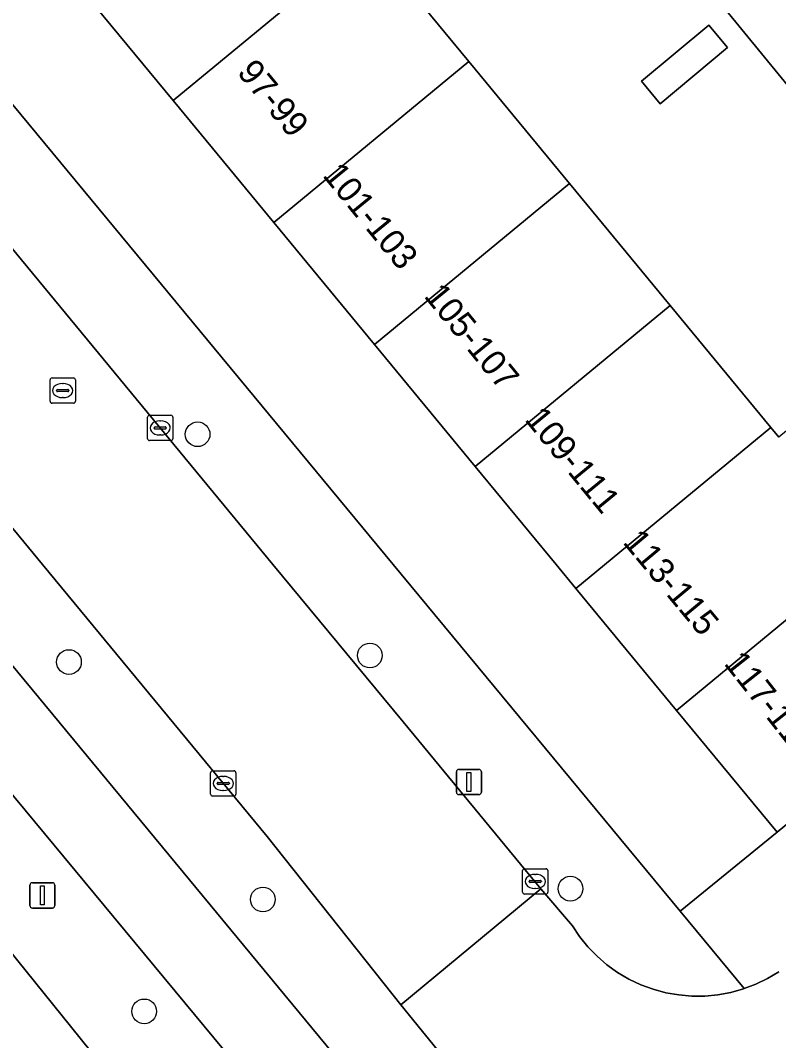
# Model space of a CAD drawing. Extents: x 159279 to 160377, y 384531 to 385888.
# Drawn here: x 159582.4 to 159612.44, y 384981.15 to 385021.54 of the extents above; entities that cross this region are included whole.
import ezdxf

# ---------------------------------------------------------------- set-up
doc = ezdxf.new("R2010")
doc.units = 0
for name, color, linetype in [('IMGEO_Berm_groen', 7, 'Continuous'), ('IMGEO_Boom', 7, 'Continuous'), ('IMGEO_Erf', 7, 'Continuous'), ('IMGEO_Fietspad_open', 7, 'Continuous'), ('IMGEO_Kolk', 7, 'Continuous'), ('IMGEO_Lichtmast', 7, 'Continuous'), ('IMGEO_Pand', 7, 'Continuous'), ('IMGEO_Pand_nummerreeks', 7, 'Continuous'), ('IMGEO_Rijbaan_lokaal_open', 7, 'Continuous'), ('IMGEO_Rioolput', 7, 'Continuous'), ('IMGEO_Voetpad_halfverhard', 7, 'Continuous'), ('IMGEO_Voetpad_open', 7, 'Continuous')]:
    doc.layers.add(name, color=color, linetype=linetype)

msp = doc.modelspace()

# ---------------------------------------------------------------- linework, layer by layer
at = {"layer": 'IMGEO_Berm_groen'}
msp.add_lwpolyline([(159548.464, 385042.144), (159514.365, 385083.398), (159506.522, 385092.845), (159505.985, 385093.489), (159501.236, 385099.246), (159500, 385098.236), (159498.552, 385097.053), (159500, 385095.299), (159503.322, 385091.276), (159555.379, 385028.229), (159578.758, 385000), (159595.338, 384979.98), (159599.426, 384980.154), (159597.476, 384982.555), (159597.475, 384982.557), (159592.173, 384989.226), (159583.28, 385000), (159567.948, 385018.574), (159561.44, 385026.479)], dxfattribs=at)
msp.add_lwpolyline([(159500.989, 385089.338), (159500, 385090.536), (159496.167, 385095.18), (159492.847, 385092.45), (159504.614, 385078.11), (159526.057, 385052.483), (159550.045, 385023.323), (159581.191, 384985.668), (159588.005, 384977.223), (159607.336, 384953.936), (159608.885, 384958.557), (159603.858, 384964.651), (159595.683, 384974.49), (159595.245, 384975.018), (159581.364, 384991.732), (159572.259, 385003.065), (159553.043, 385026.266)], close=True, dxfattribs=at)
at = {"layer": 'IMGEO_Boom'}
for centre in [(159589.42, 385005.154), (159596.245, 384996.395), (159584.325, 384996.135), (159604.191, 384987.161), (159592.006, 384986.734), (159587.306, 384982.303)]:
    msp.add_circle(centre, 0.489, dxfattribs=at)
at = {"layer": 'IMGEO_Erf'}
msp.add_lwpolyline([(159616.978, 385013.863), (159607.326, 385025.657), (159605.604, 385024.219), (159603.943, 385026.208), (159605.684, 385027.662), (159579.473, 385059.689), (159572.244, 385053.719), (159576.232, 385048.89), (159580.22, 385044.06), (159584.208, 385039.231), (159588.197, 385034.402), (159592.185, 385029.572), (159596.173, 385024.743), (159600.161, 385019.914), (159604.149, 385015.084), (159608.138, 385010.255), (159612.126, 385005.425), (159612.45, 385005.033)], dxfattribs=at)
for points in [[(159588.454, 385018.369), (159584.466, 385023.198), (159580.478, 385028.027), (159576.49, 385032.857), (159572.501, 385037.686), (159568.513, 385042.516), (159564.525, 385047.345), (159560.632, 385044.131), (159597.171, 385000), (159608.541, 384986.268), (159612.383, 384989.392), (159608.395, 384994.221), (159604.407, 384999.051), (159603.623, 385000), (159600.419, 385003.88), (159596.43, 385008.71), (159592.442, 385013.539)], [(159607.006, 385019.132), (159609.671, 385021.357), (159610.415, 385020.465), (159607.75, 385018.241)]]:
    msp.add_lwpolyline(points, close=True, dxfattribs=at)
at = {"layer": 'IMGEO_Fietspad_open'}
msp.add_lwpolyline([(159503.322, 385091.276), (159500, 385095.299), (159498.552, 385097.053), (159496.167, 385095.18), (159500, 385090.536), (159500.989, 385089.338), (159553.043, 385026.266), (159572.259, 385003.065), (159581.364, 384991.732), (159595.245, 384975.018), (159597.738, 384977.083), (159601.819, 384977.205), (159599.426, 384980.154), (159595.338, 384979.98), (159578.758, 385000), (159555.379, 385028.229)], close=True, dxfattribs=at)
at = {"layer": 'IMGEO_Kolk'}
for p, q in [((159587.438, 385004.979), (159587.438, 385005.831)), ((159587.513, 385005.905), (159588.365, 385005.905)), ((159587.926, 385005.685), (159587.951, 385005.685)), ((159588.439, 385005.831), (159588.439, 385004.979)), ((159587.697, 385005.399), (159587.697, 385005.411)), ((159588.135, 385005.362), (159587.737, 385005.362)), ((159587.74, 385005.448), (159588.138, 385005.448)), ((159588.181, 385005.411), (159588.181, 385005.399)), ((159588.365, 385004.905), (159587.513, 385004.905)), ((159587.949, 385005.125), (159587.924, 385005.125)), ((159589.935, 384990.902), (159589.935, 384991.754)), ((159590.01, 384991.828), (159590.862, 384991.828)), ((159590.423, 384991.608), (159590.448, 384991.608)), ((159590.936, 384991.754), (159590.936, 384990.902)), ((159590.194, 384991.322), (159590.194, 384991.334)), ((159590.632, 384991.285), (159590.234, 384991.285)), ((159590.237, 384991.371), (159590.635, 384991.371)), ((159590.678, 384991.334), (159590.678, 384991.322)), ((159590.862, 384990.828), (159590.01, 384990.828)), ((159590.446, 384991.048), (159590.421, 384991.048)), ((159602.369, 384987.948), (159603.221, 384987.948)), ((159602.294, 384987.022), (159602.294, 384987.874)), ((159602.782, 384987.728), (159602.807, 384987.728)), ((159603.295, 384987.874), (159603.295, 384987.022)), ((159602.553, 384987.442), (159602.553, 384987.454)), ((159602.991, 384987.405), (159602.593, 384987.405)), ((159602.596, 384987.491), (159602.994, 384987.491)), ((159602.805, 384987.168), (159602.78, 384987.168)), ((159603.037, 384987.454), (159603.037, 384987.442)), ((159603.221, 384986.948), (159602.369, 384986.948))]:
    msp.add_line(p, q, dxfattribs=at)
for points in [[(159587.438, 385004.979), (159587.438, 385005.831)], [(159587.513, 385005.905), (159588.365, 385005.905)], [(159588.439, 385005.831), (159588.439, 385004.979)], [(159588.365, 385004.905), (159587.513, 385004.905)], [(159589.935, 384990.902), (159589.935, 384991.754)], [(159590.01, 384991.828), (159590.862, 384991.828)], [(159590.936, 384991.754), (159590.936, 384990.902)], [(159590.862, 384990.828), (159590.01, 384990.828)], [(159602.369, 384987.948), (159603.221, 384987.948)], [(159602.294, 384987.022), (159602.294, 384987.874)], [(159603.295, 384987.874), (159603.295, 384987.022)], [(159603.221, 384986.948), (159602.369, 384986.948)]]:
    msp.add_lwpolyline(points, dxfattribs=at)
for centre, radius, start, end in [((159587.515, 385005.829), 0.0765, 91.552, 178.448), ((159587.515, 385005.829), 0.0765, 91.552, 178.448), ((159588.363, 385005.829), 0.0765, 1.552, 88.448), ((159588.363, 385005.829), 0.0765, 1.552, 88.448), ((159587.737, 385005.408), 0.0403, 85.8775, 175.7526), ((159587.734, 385005.398), 0.0366, 178.938, 274.7102), ((159588.138, 385005.405), 0.043, 264.8664, 352.4533), ((159588.142, 385005.41), 0.0386, 1.7309, 96.639), ((159587.515, 385004.981), 0.0765, 181.552, 268.448), ((159587.515, 385004.981), 0.0765, 181.552, 268.448), ((159588.363, 385004.981), 0.0765, 271.552, 358.448), ((159588.363, 385004.981), 0.0765, 271.552, 358.448), ((159590.012, 384991.752), 0.0765, 91.552, 178.448), ((159590.012, 384991.752), 0.0765, 91.552, 178.448), ((159590.86, 384991.752), 0.0765, 1.552, 88.448), ((159590.86, 384991.752), 0.0765, 1.552, 88.448), ((159590.234, 384991.331), 0.0403, 85.8775, 175.7526), ((159590.231, 384991.321), 0.0366, 178.938, 274.7102), ((159590.635, 384991.328), 0.043, 264.8664, 352.4533), ((159590.639, 384991.333), 0.0386, 1.7309, 96.639), ((159590.012, 384990.904), 0.0765, 181.552, 268.448), ((159590.012, 384990.904), 0.0765, 181.552, 268.448), ((159590.86, 384990.904), 0.0765, 271.552, 358.448), ((159590.86, 384990.904), 0.0765, 271.552, 358.448), ((159602.371, 384987.872), 0.0765, 91.552, 178.448), ((159602.371, 384987.872), 0.0765, 91.552, 178.448), ((159603.219, 384987.872), 0.0765, 1.552, 88.448), ((159603.219, 384987.872), 0.0765, 1.552, 88.448), ((159602.593, 384987.451), 0.0403, 85.8775, 175.7526), ((159602.59, 384987.441), 0.0366, 178.938, 274.7102), ((159602.994, 384987.448), 0.043, 264.8664, 352.4533), ((159602.998, 384987.453), 0.0386, 1.7309, 96.639), ((159602.371, 384987.024), 0.0765, 181.552, 268.448), ((159602.371, 384987.024), 0.0765, 181.552, 268.448), ((159603.219, 384987.024), 0.0765, 271.552, 358.448), ((159603.219, 384987.024), 0.0765, 271.552, 358.448)]:
    msp.add_arc(centre, radius, start, end, dxfattribs=at)
for centre, major_axis, ratio, start_param, end_param in [((159587.925, 385005.405), (-0.387, 0.002), 0.722429, 4.712389, 7.853982), ((159587.95, 385005.405), (-0.39, 0.002), 0.717154, 1.570796, 4.712389), ((159590.422, 384991.328), (-0.387, 0.002), 0.722429, 4.712389, 7.853982), ((159590.447, 384991.328), (-0.39, 0.002), 0.717154, 1.570796, 4.712389), ((159602.781, 384987.448), (-0.387, 0.002), 0.722429, 4.712389, 7.853982), ((159602.806, 384987.448), (-0.39, 0.002), 0.717154, 1.570796, 4.712389)]:
    msp.add_ellipse(centre, major_axis=major_axis, ratio=ratio, start_param=start_param, end_param=end_param, dxfattribs=at)
at = {"layer": 'IMGEO_Lichtmast'}
for p, q in [((159599.672, 384990.984), (159599.672, 384991.784)), ((159599.672, 384991.784), (159599.672, 384990.984)), ((159599.772, 384991.884), (159600.562, 384991.884)), ((159600.562, 384991.884), (159599.772, 384991.884)), ((159600.662, 384991.784), (159600.662, 384990.984)), ((159600.662, 384990.984), (159600.662, 384991.784)), ((159600.562, 384990.884), (159599.772, 384990.884)), ((159599.772, 384990.884), (159600.562, 384990.884)), ((159582.776, 384986.494), (159582.776, 384987.294)), ((159582.776, 384987.294), (159582.776, 384986.494)), ((159582.876, 384987.394), (159583.666, 384987.394)), ((159583.666, 384987.394), (159582.876, 384987.394)), ((159583.766, 384987.294), (159583.766, 384986.494)), ((159583.766, 384986.494), (159583.766, 384987.294)), ((159583.666, 384986.394), (159582.876, 384986.394)), ((159582.876, 384986.394), (159583.666, 384986.394))]:
    msp.add_line(p, q, dxfattribs=at)
for points in [[(159600.092, 384991.759), (159600.242, 384991.759), (159600.242, 384991.009), (159600.092, 384991.009), (159600.092, 384991.759)], [(159583.196, 384987.269), (159583.346, 384987.269), (159583.346, 384986.519), (159583.196, 384986.519), (159583.196, 384987.269)]]:
    msp.add_lwpolyline(points, dxfattribs=at)
for centre, start, end in [((159599.772, 384991.784), 90, 180), ((159599.772, 384991.784), 90, 180), ((159600.562, 384991.784), 0, 90), ((159600.562, 384991.784), 360, 90), ((159599.772, 384990.984), 180, 270), ((159599.772, 384990.984), 180, 270), ((159600.562, 384990.984), 270, 0), ((159600.562, 384990.984), 270, 0), ((159582.876, 384987.294), 90, 180), ((159582.876, 384987.294), 90, 180), ((159583.666, 384987.294), 0, 90), ((159583.666, 384987.294), 360, 90), ((159582.876, 384986.494), 180, 270), ((159582.876, 384986.494), 180, 270), ((159583.666, 384986.494), 270, 0), ((159583.666, 384986.494), 270, 0)]:
    msp.add_arc(centre, 0.1, start, end, dxfattribs=at)
at = {"layer": 'IMGEO_Pand'}
for points in [[(159588.454, 385018.369), (159596.173, 385024.743), (159592.185, 385029.572), (159584.466, 385023.198)], [(159592.442, 385013.539), (159600.161, 385019.914), (159596.173, 385024.743), (159588.454, 385018.369)], [(159607.006, 385019.132), (159607.75, 385018.241), (159610.415, 385020.465), (159609.671, 385021.357)], [(159596.43, 385008.71), (159604.149, 385015.084), (159600.161, 385019.914), (159592.442, 385013.539)], [(159600.419, 385003.88), (159608.138, 385010.255), (159604.149, 385015.084), (159596.43, 385008.71)], [(159604.407, 384999.051), (159612.126, 385005.425), (159608.138, 385010.255), (159600.419, 385003.88), (159603.623, 385000)], [(159616.114, 385000.596), (159615.405, 385001.455), (159617.226, 385002.959), (159614.271, 385006.537), (159612.45, 385005.033), (159612.126, 385005.425), (159604.407, 384999.051), (159608.395, 384994.221)], [(159612.383, 384989.392), (159617.745, 384993.821), (159619.535, 384996.454), (159616.606, 385000), (159616.114, 385000.596), (159608.395, 384994.221)]]:
    msp.add_lwpolyline(points, close=True, dxfattribs=at)
at = {"layer": 'IMGEO_Rijbaan_lokaal_open'}
for points in [[(159561.44, 385026.479), (159567.948, 385018.574), (159583.28, 385000), (159592.173, 384989.226), (159597.475, 384982.557), (159597.476, 384982.555), (159603.013, 384987.157), (159597.557, 384993.768), (159592.405, 385000), (159575.522, 385020.423), (159570.914, 385025.995)], [(159612.444, 384983.873), (159611.998, 384983.605), (159611.531, 384983.378), (159611.076, 384983.206), (159611.045, 384983.194), (159610.544, 384983.054), (159610.033, 384982.959), (159609.516, 384982.91), (159608.996, 384982.908), (159608.478, 384982.952), (159607.967, 384983.042), (159607.465, 384983.178), (159606.977, 384983.358), (159606.508, 384983.58), (159606.06, 384983.844), (159605.637, 384984.147), (159605.244, 384984.486), (159604.882, 384984.859), (159604.555, 384985.263), (159604.265, 384985.694), (159603.013, 384987.157), (159597.476, 384982.555), (159599.426, 384980.154)]]:
    msp.add_lwpolyline(points, dxfattribs=at)
at = {"layer": 'IMGEO_Rioolput'}
for p, q in [((159583.578, 385006.458), (159583.578, 385007.31)), ((159583.653, 385007.384), (159584.505, 385007.384)), ((159584.579, 385007.31), (159584.579, 385006.458)), ((159583.837, 385006.878), (159583.837, 385006.89)), ((159583.88, 385006.927), (159584.278, 385006.927)), ((159584.066, 385007.164), (159584.091, 385007.164)), ((159584.321, 385006.89), (159584.321, 385006.878)), ((159584.275, 385006.841), (159583.877, 385006.841)), ((159584.089, 385006.604), (159584.064, 385006.604)), ((159584.505, 385006.384), (159583.653, 385006.384))]:
    msp.add_line(p, q, dxfattribs=at)
for points in [[(159583.578, 385006.458), (159583.578, 385007.31)], [(159583.653, 385007.384), (159584.505, 385007.384)], [(159584.579, 385007.31), (159584.579, 385006.458)], [(159584.505, 385006.384), (159583.653, 385006.384)]]:
    msp.add_lwpolyline(points, dxfattribs=at)
for centre, radius, start, end in [((159583.655, 385007.308), 0.0765, 91.552, 178.448), ((159583.655, 385007.308), 0.0765, 91.552, 178.448), ((159584.503, 385007.308), 0.0765, 1.552, 88.448), ((159584.503, 385007.308), 0.0765, 1.552, 88.448), ((159583.877, 385006.887), 0.0403, 85.8775, 175.7526), ((159584.282, 385006.889), 0.0386, 1.7309, 96.639), ((159583.874, 385006.877), 0.0366, 178.938, 274.7102), ((159584.278, 385006.884), 0.043, 264.8664, 352.4533), ((159583.655, 385006.46), 0.0765, 181.552, 268.448), ((159583.655, 385006.46), 0.0765, 181.552, 268.448), ((159584.503, 385006.46), 0.0765, 271.552, 358.448), ((159584.503, 385006.46), 0.0765, 271.552, 358.448)]:
    msp.add_arc(centre, radius, start, end, dxfattribs=at)
for centre, major_axis, ratio, start_param, end_param in [((159584.065, 385006.884), (-0.387, 0.002), 0.722429, 4.712389, 7.853982), ((159584.09, 385006.884), (-0.39, 0.002), 0.717154, 1.570796, 4.712389)]:
    msp.add_ellipse(centre, major_axis=major_axis, ratio=ratio, start_param=start_param, end_param=end_param, dxfattribs=at)
at = {"layer": 'IMGEO_Voetpad_halfverhard'}
msp.add_lwpolyline([(159492.847, 385092.45), (159490.493, 385090.52), (159501.009, 385077.693), (159516.518, 385059.136), (159548.14, 385020.507), (159580.094, 384981.698), (159581.213, 384980.339), (159607.67, 384948.458), (159609.789, 384950.769), (159611.069, 384955.91), (159609.221, 384958.15), (159608.885, 384958.557), (159607.336, 384953.936), (159588.005, 384977.223), (159581.191, 384985.668), (159550.045, 385023.323), (159526.057, 385052.483), (159504.614, 385078.11)], close=True, dxfattribs=at)
at = {"layer": 'IMGEO_Voetpad_open'}
for points in [[(159587.133, 385072.965), (159580.752, 385063.798), (159570.691, 385055.496), (159566.826, 385052.307), (159562.969, 385049.125), (159559.124, 385045.952), (159560.632, 385044.131), (159564.525, 385047.345), (159568.381, 385050.529), (159572.244, 385053.719), (159579.473, 385059.689), (159605.684, 385027.662), (159605.919, 385027.858), (159607.58, 385025.869), (159607.326, 385025.657), (159616.978, 385013.863)], [(159575.522, 385020.423), (159592.405, 385000), (159597.557, 384993.768), (159603.013, 384987.157), (159604.265, 384985.694), (159604.555, 384985.263), (159604.882, 384984.859), (159605.244, 384984.486), (159605.637, 384984.147), (159606.06, 384983.844), (159606.508, 384983.58), (159606.977, 384983.358), (159607.465, 384983.178), (159607.967, 384983.042), (159608.478, 384982.952), (159608.996, 384982.908), (159609.516, 384982.91), (159610.033, 384982.959), (159610.544, 384983.054), (159611.045, 384983.194), (159611.076, 384983.206), (159608.541, 384986.268), (159597.171, 385000), (159560.632, 385044.131)], [(159617.745, 384993.821), (159612.383, 384989.392), (159608.541, 384986.268), (159611.076, 384983.206), (159611.531, 384983.378), (159611.998, 384983.605), (159612.444, 384983.873)]]:
    msp.add_lwpolyline(points, dxfattribs=at)

# ---------------------------------------------------------------- texts
at = {"layer": 'IMGEO_Pand_nummerreeks'}
for s, rotation, p in [('97-99', 309.4709, (159590.951, 385019.47)), ('101-103', 309.2531, (159594.341, 385015.394)), ('105-107', 309.1443, (159598.356, 385010.619)), ('109-111', 309.4021, (159602.346, 385005.728)), ('113-115', 309.8719, (159606.233, 385000.866)), ('117-119', 308.3307, (159610.241, 384996.068))]:
    msp.add_text(s, height=1, rotation=rotation, dxfattribs=at).set_placement(p)

doc.saveas('drawing.dxf')
